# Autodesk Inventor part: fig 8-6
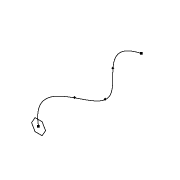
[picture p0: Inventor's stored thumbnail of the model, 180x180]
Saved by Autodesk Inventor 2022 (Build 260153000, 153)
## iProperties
Created: 2006-01
Part Number: fig 8-6
Document SubType Name: Modeling
Designer: CADCIM
Density: 1 g/cm^3
Material: Generic
Appearance: Default
Author: CADCIM
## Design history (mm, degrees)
sketch "Sketch1"
  geometry: 5 further points
  constraints: 5 other
sketch "Sketch2"
  geometry: L1 (-4.728, 0)-(-2.364, 4.094); L2 (-2.364, 4.094)-(2.364, 4.094); L3 (2.364, 4.094)-(4.728, 0); L4 (4.728, 0)-(2.364, -4.094); L5 (2.364, -4.094)-(-2.364, -4.094); L6 (-2.364, -4.094)-(-4.728, 0); 1 further point
  constraints: 12 end point, 13 other
body "Solid1"
